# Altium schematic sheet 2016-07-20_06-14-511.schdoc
size 252 x 172 mm; SheetNumber: 1; SheetTotal: 1
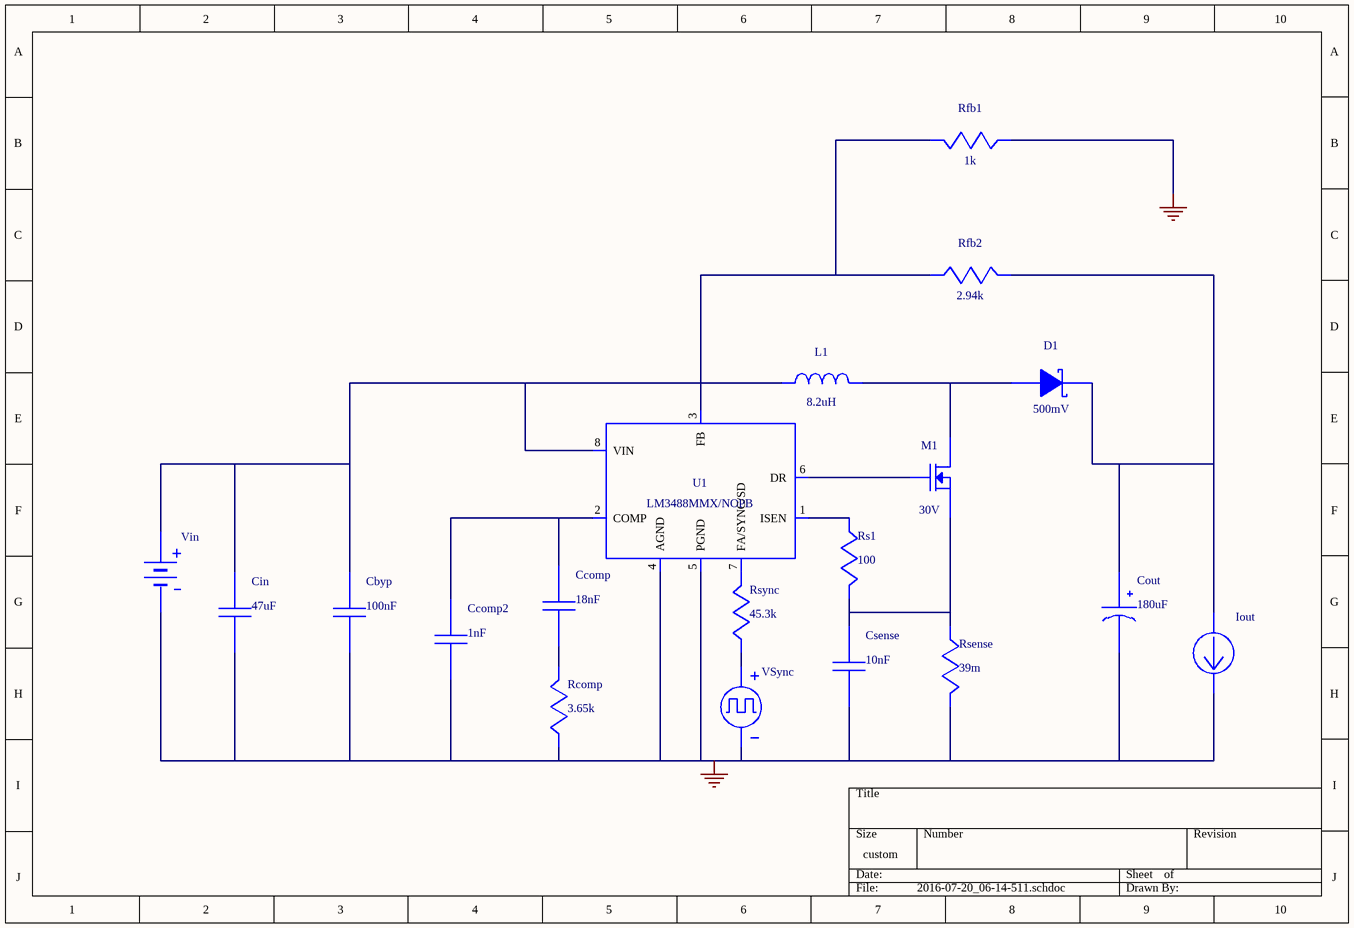
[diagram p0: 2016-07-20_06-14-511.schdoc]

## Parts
Cbyp  value 100nF  (hidden comment: GRM155R60J104KA01D)
Ccomp  value 18nF  (hidden comment: CC0805KRX7R9BB183)
Ccomp2  value 1nF  (hidden comment: CL21C102JBCNFNC)
Cin  value 47uF  (hidden comment: GRM31CC80J476KE18L)
Cout  value 180uF  (hidden comment: 16SVPF180M)
Csense  value 10nF  (hidden comment: GRM216R71H103KA01D)
D1  value 500mV  (hidden comment: B220-13-F)
Iout  WB_CURRENT_LOAD  (value not drawn)
L1  value 8.2uH  (hidden comment: SRN6045-8R2Y)
M1  value 30V  (hidden comment: CSD17308Q3)
Rcomp  value 3.65k  (hidden comment: CRCW04023K65FKED)
Rfb1  value 1k  (hidden comment: CRCW04021K00FKED)
Rfb2  value 2.94k  (hidden comment: CRCW04022K94FKED)
Rs1  value 100  (hidden comment: CRCW0402100RFKED)
Rsense  value 39m  (hidden comment: ERJ-L14KF39MU)
Rsync  value 45.3k  (hidden comment: CRCW040245K3FKED)
U1  LM3488MM/NOPB  (value not drawn)
Vin  WB_BATTERY  (value not drawn)
VSync  WB_SYNC_SOURCE  (value not drawn)

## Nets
0: Cbyp.2 Ccomp2.2 Cin.2 Cout.2(-) Csense.2 Iout.2(-) Rcomp.2 Rfb1.2 Rsense.1 U1.4(AGND) U1.5(PGND) Vin.2(-) VSync.2(-)
NetCbyp_1: Cbyp.1 Cin.1 L1.1 U1.8(VIN) Vin.1(+)
NetCcomp_1: Ccomp.1 Ccomp2.1 U1.2(COMP)
NetCcomp_2: Ccomp.2 Rcomp.1
NetCout_1: Cout.1(+) D1.1(K) Iout.1(+) Rfb2.1
NetCsense_1: Csense.1 M1.1(Source) M1.2(Source) M1.3(Source) Rs1.1 Rsense.2
NetD1_2: D1.2(A) L1.2 M1.5(Drain) M1.6(Drain) M1.7(Drain) M1.8(Drain) M1.9(Drain)
NetM1_4: M1.4(Gate) U1.6(DR)
NetRfb1_1: Rfb1.1 Rfb2.2 U1.3(FB)
NetRs1_2: Rs1.2 U1.1(ISEN)
NetRsync_1: Rsync.1 U1.7(FA/SYNC/SD)
NetRsync_2: Rsync.2 VSync.1(+)

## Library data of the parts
Cbyp = GRM155R60J104KA01D: GRM155R60J104KA0; Manufacturer Name: MuRata
Ccomp = CC0805KRX7R9BB183: CC0805KRX7R9BB18; Manufacturer Name: Yageo America
Ccomp2 = CL21C102JBCNFNC: Manufacturer Name: Samsung Electro-Mechanics
Cin = GRM31CC80J476KE18L: GRM31CC80J476KE1; Manufacturer Name: MuRata
Cout = 16SVPF180M: Manufacturer Name: Panasonic
Csense = GRM216R71H103KA01D: GRM216R71H103KA0; Manufacturer Name: MuRata
D1 = B220-13-F: Manufacturer Name: Diodes Inc.
L1 = SRN6045-8R2Y: Manufacturer Name: Bourns
M1 = CSD17308Q3: Manufacturer Name: Texas Instruments
Rcomp = CRCW04023K65FKED: Manufacturer Name: Vishay-Dale
Rfb1 = CRCW04021K00FKED: Manufacturer Name: Vishay-Dale
Rfb2 = CRCW04022K94FKED: Manufacturer Name: Vishay-Dale
Rs1 = CRCW0402100RFKED: Manufacturer Name: Vishay-Dale
Rsense = ERJ-L14KF39MU: Manufacturer Name: Panasonic
Rsync = CRCW040245K3FKED: Manufacturer Name: Vishay-Dale
U1 = LM3488MM/NOPB: LM3488MMX/NOPB; Manufacturer Name: Texas Instruments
